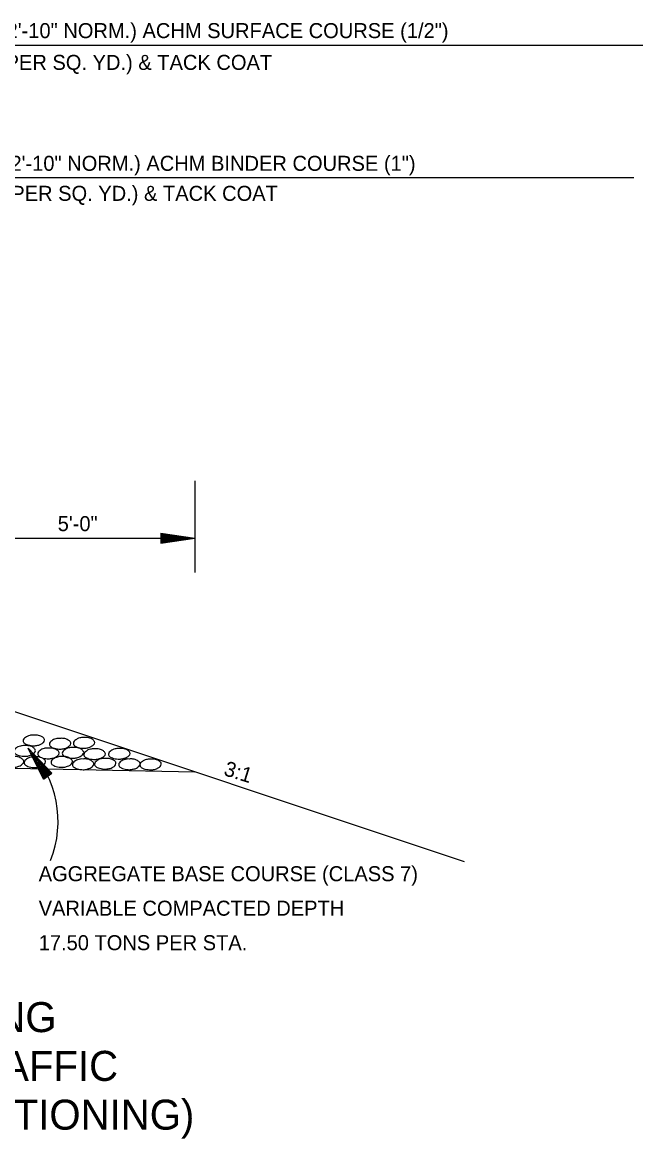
# Model space of a CAD drawing. Extents: x 635488 to 635865, y 290537 to 290973.
# Drawn here: x 635544.25 to 635569.05, y 290815.29 to 290859.93 of the extents above; entities that cross this region are included whole.
import ezdxf

# ---------------------------------------------------------------- set-up
doc = ezdxf.new("R2010")
doc.units = 0
doc.layers.add('Default', color=7, linetype='Continuous')

msp = doc.modelspace()

# ---------------------------------------------------------------- linework, layer by layer
at = {"layer": 'Default'}
for p, q in [((635569.047, 290859.005), (635537.821, 290859.005)), ((635568.697, 290853.718), (635538.128, 290853.718)), ((635551.153, 290841.602), (635551.153, 290837.937)), ((635549.785, 290839.511), (635551.153, 290839.307)), ((635549.785, 290839.511), (635549.785, 290839.101)), ((635549.785, 290839.478), (635550.924, 290839.307)), ((635542.16, 290839.307), (635551.153, 290839.307)), ((635549.785, 290839.442), (635550.687, 290839.307)), ((635549.785, 290839.409), (635550.458, 290839.307)), ((635549.785, 290839.372), (635550.227, 290839.307)), ((635549.785, 290839.339), (635549.998, 290839.307)), ((635549.785, 290839.101), (635551.153, 290839.307)), ((635549.785, 290839.238), (635550.227, 290839.307)), ((635549.785, 290839.169), (635550.687, 290839.307)), ((635549.785, 290839.135), (635550.924, 290839.307)), ((635549.785, 290839.205), (635550.458, 290839.307)), ((635549.785, 290839.274), (635549.998, 290839.307)), ((635542.16, 290832.959), (635561.914, 290826.375)), ((635512.523, 290830.734), (635551.153, 290829.962)), ((635545.095, 290829.669), (635544.483, 290830.911)), ((635545.433, 290829.906), (635544.483, 290830.911)), ((635545.123, 290829.687), (635544.615, 290830.724)), ((635545.405, 290829.882), (635544.615, 290830.724)), ((635545.376, 290829.865), (635544.749, 290830.529)), ((635545.153, 290829.708), (635544.749, 290830.529)), ((635545.182, 290829.728), (635544.878, 290830.342)), ((635545.347, 290829.843), (635544.878, 290830.342)), ((635545.319, 290829.825), (635545.012, 290830.152)), ((635545.21, 290829.75), (635545.012, 290830.152)), ((635545.095, 290829.669), (635545.433, 290829.906)), ((635545.29, 290829.804), (635545.142, 290829.966)), ((635545.238, 290829.767), (635545.142, 290829.966))]:
    msp.add_line(p, q, dxfattribs=at)
msp.add_arc((635541.498, 290827.979), 4.183, 337.9932, 44.4822, dxfattribs=at)
for points in [[(635544.705, 290831.429), (635544.858, 290831.428), (635545.04, 290831.364), (635545.129, 290831.281), (635545.141, 290831.227), (635545.095, 290831.135), (635545.043, 290831.096), (635544.943, 290831.044), (635544.797, 290831.01), (635544.721, 290831.002), (635544.61, 290831.013), (635544.484, 290831.034), (635544.389, 290831.071), (635544.301, 290831.144), (635544.286, 290831.202), (635544.312, 290831.284), (635544.382, 290831.337), (635544.446, 290831.379), (635544.548, 290831.414), (635544.611, 290831.428), (635544.705, 290831.429)], [(635544.342, 290831.008), (635544.49, 290831.007), (635544.674, 290830.944), (635544.761, 290830.857), (635544.777, 290830.807), (635544.73, 290830.714), (635544.676, 290830.673), (635544.577, 290830.625), (635544.431, 290830.587), (635544.353, 290830.583), (635544.244, 290830.589), (635544.119, 290830.609), (635544.024, 290830.65), (635543.935, 290830.72), (635543.921, 290830.779), (635543.949, 290830.862), (635544.018, 290830.918), (635544.079, 290830.961), (635544.182, 290830.991), (635544.246, 290831.007), (635544.342, 290831.008)], [(635545.753, 290831.298), (635545.904, 290831.297), (635546.086, 290831.233), (635546.178, 290831.147), (635546.192, 290831.097), (635546.142, 290831.004), (635546.09, 290830.962), (635545.993, 290830.913), (635545.842, 290830.876), (635545.768, 290830.871), (635545.655, 290830.879), (635545.533, 290830.901), (635545.438, 290830.94), (635545.349, 290831.01), (635545.335, 290831.072), (635545.362, 290831.15), (635545.43, 290831.206), (635545.496, 290831.25), (635545.594, 290831.283), (635545.656, 290831.297), (635545.753, 290831.298)], [(635546.71, 290831.33), (635546.861, 290831.328), (635547.045, 290831.266), (635547.132, 290831.18), (635547.146, 290831.13), (635547.098, 290831.035), (635547.047, 290830.995), (635546.947, 290830.946), (635546.8, 290830.909), (635546.724, 290830.904), (635546.613, 290830.912), (635546.489, 290830.934), (635546.392, 290830.973), (635546.303, 290831.043), (635546.291, 290831.101), (635546.319, 290831.183), (635546.388, 290831.238), (635546.45, 290831.281), (635546.551, 290831.316), (635546.615, 290831.328), (635546.71, 290831.33)], [(635543.875, 290830.569), (635544.026, 290830.568), (635544.208, 290830.504), (635544.3, 290830.418), (635544.314, 290830.368), (635544.264, 290830.275), (635544.211, 290830.233), (635544.115, 290830.184), (635543.964, 290830.147), (635543.89, 290830.142), (635543.777, 290830.15), (635543.655, 290830.172), (635543.56, 290830.211), (635543.471, 290830.281), (635543.457, 290830.343), (635543.484, 290830.421), (635543.552, 290830.477), (635543.618, 290830.521), (635543.716, 290830.554), (635543.778, 290830.568), (635543.875, 290830.569)], [(635544.746, 290830.56), (635544.897, 290830.558), (635545.079, 290830.494), (635545.171, 290830.408), (635545.185, 290830.358), (635545.135, 290830.265), (635545.082, 290830.223), (635544.986, 290830.175), (635544.834, 290830.137), (635544.761, 290830.133), (635544.647, 290830.14), (635544.526, 290830.162), (635544.431, 290830.201), (635544.342, 290830.271), (635544.328, 290830.334), (635544.355, 290830.411), (635544.423, 290830.468), (635544.489, 290830.511), (635544.587, 290830.544), (635544.649, 290830.558), (635544.746, 290830.56)], [(635545.286, 290830.91), (635545.437, 290830.909), (635545.619, 290830.845), (635545.711, 290830.759), (635545.725, 290830.709), (635545.675, 290830.616), (635545.623, 290830.574), (635545.526, 290830.526), (635545.375, 290830.488), (635545.302, 290830.483), (635545.188, 290830.491), (635545.066, 290830.513), (635544.971, 290830.552), (635544.882, 290830.622), (635544.868, 290830.684), (635544.895, 290830.762), (635544.963, 290830.818), (635545.029, 290830.862), (635545.127, 290830.895), (635545.189, 290830.909), (635545.286, 290830.91)], [(635545.821, 290830.569), (635545.972, 290830.568), (635546.155, 290830.504), (635546.247, 290830.418), (635546.261, 290830.368), (635546.211, 290830.275), (635546.158, 290830.233), (635546.061, 290830.184), (635545.91, 290830.147), (635545.837, 290830.142), (635545.723, 290830.15), (635545.601, 290830.172), (635545.506, 290830.211), (635545.418, 290830.281), (635545.404, 290830.343), (635545.43, 290830.421), (635545.499, 290830.477), (635545.564, 290830.521), (635545.662, 290830.554), (635545.725, 290830.568), (635545.821, 290830.569)], [(635546.269, 290830.932), (635546.42, 290830.93), (635546.604, 290830.868), (635546.692, 290830.78), (635546.704, 290830.731), (635546.659, 290830.639), (635546.606, 290830.595), (635546.506, 290830.548), (635546.358, 290830.512), (635546.285, 290830.505), (635546.171, 290830.514), (635546.046, 290830.534), (635545.954, 290830.573), (635545.863, 290830.643), (635545.85, 290830.703), (635545.878, 290830.785), (635545.945, 290830.84), (635546.009, 290830.885), (635546.11, 290830.916), (635546.174, 290830.93), (635546.269, 290830.932)], [(635547.135, 290830.881), (635547.284, 290830.88), (635547.465, 290830.817), (635547.556, 290830.73), (635547.571, 290830.682), (635547.523, 290830.588), (635547.468, 290830.545), (635547.37, 290830.5), (635547.222, 290830.464), (635547.147, 290830.456), (635547.038, 290830.465), (635546.912, 290830.486), (635546.818, 290830.523), (635546.727, 290830.593), (635546.714, 290830.654), (635546.742, 290830.736), (635546.811, 290830.791), (635546.873, 290830.835), (635546.974, 290830.864), (635547.04, 290830.88), (635547.135, 290830.881)], [(635548.119, 290830.893), (635548.27, 290830.892), (635548.454, 290830.831), (635548.543, 290830.744), (635548.557, 290830.695), (635548.508, 290830.599), (635548.455, 290830.558), (635548.356, 290830.513), (635548.208, 290830.476), (635548.134, 290830.469), (635548.021, 290830.477), (635547.897, 290830.498), (635547.804, 290830.536), (635547.712, 290830.608), (635547.701, 290830.666), (635547.728, 290830.747), (635547.795, 290830.803), (635547.86, 290830.847), (635547.96, 290830.879), (635548.024, 290830.892), (635548.119, 290830.893)], [(635546.673, 290830.473), (635546.824, 290830.472), (635547.007, 290830.408), (635547.098, 290830.322), (635547.112, 290830.272), (635547.063, 290830.179), (635547.01, 290830.137), (635546.913, 290830.088), (635546.762, 290830.051), (635546.689, 290830.046), (635546.575, 290830.054), (635546.453, 290830.076), (635546.358, 290830.115), (635546.269, 290830.185), (635546.255, 290830.247), (635546.282, 290830.325), (635546.35, 290830.381), (635546.416, 290830.425), (635546.514, 290830.458), (635546.576, 290830.472), (635546.673, 290830.473)], [(635547.559, 290830.497), (635547.71, 290830.495), (635547.891, 290830.433), (635547.983, 290830.345), (635547.994, 290830.297), (635547.948, 290830.202), (635547.895, 290830.162), (635547.797, 290830.113), (635547.648, 290830.076), (635547.573, 290830.07), (635547.461, 290830.081), (635547.338, 290830.101), (635547.241, 290830.138), (635547.154, 290830.211), (635547.138, 290830.269), (635547.165, 290830.35), (635547.235, 290830.406), (635547.299, 290830.448), (635547.401, 290830.481), (635547.462, 290830.495), (635547.559, 290830.497)], [(635548.524, 290830.473), (635548.674, 290830.472), (635548.856, 290830.408), (635548.948, 290830.324), (635548.961, 290830.271), (635548.912, 290830.179), (635548.858, 290830.137), (635548.763, 290830.087), (635548.611, 290830.056), (635548.538, 290830.045), (635548.424, 290830.057), (635548.303, 290830.077), (635548.209, 290830.116), (635548.119, 290830.185), (635548.103, 290830.246), (635548.132, 290830.327), (635548.2, 290830.383), (635548.266, 290830.425), (635548.364, 290830.456), (635548.426, 290830.472), (635548.524, 290830.473)], [(635549.372, 290830.466), (635549.525, 290830.465), (635549.707, 290830.401), (635549.796, 290830.318), (635549.808, 290830.264), (635549.762, 290830.172), (635549.71, 290830.133), (635549.61, 290830.081), (635549.464, 290830.047), (635549.388, 290830.039), (635549.277, 290830.05), (635549.151, 290830.071), (635549.056, 290830.108), (635548.968, 290830.181), (635548.953, 290830.239), (635548.979, 290830.321), (635549.049, 290830.374), (635549.113, 290830.416), (635549.215, 290830.451), (635549.278, 290830.465), (635549.372, 290830.466)]]:
    msp.add_spline(points, degree=3, dxfattribs=at)

# ---------------------------------------------------------------- texts
for s, height, p in [('VAR. (12\'-10" NORM.) ACHM SURFACE COURSE (1/2")', 0.6, (635540.815, 290859.302)), ('(XXX LBS. PER SQ. YD.) & TACK COAT', 0.6, (635539.525, 290858.032)), ('VAR. (12\'-10" NORM.) ACHM BINDER COURSE (1")', 0.6, (635540.97, 290853.995)), ('(XXX LBS. PER SQ. YD.) & TACK COAT', 0.6, (635539.753, 290852.795)), ('5\'-0"', 0.6, (635545.666, 290839.587)), ('AGGREGATE BASE COURSE (CLASS 7)', 0.6, (635544.906, 290825.587)), ('VARIABLE COMPACTED DEPTH', 0.6, (635544.906, 290824.208)), ('17.50 TONS PER STA.', 0.6, (635544.906, 290822.829)), ('ADDITIONAL WIDENING ', 1.2, (635527.344, 290819.552)), ('FOR MAINTENANCE OF TRAFFIC', 1.2, (635522.673, 290817.602)), ('(SHOWN IN DIRECTION OF STATIONING)', 1.2, (635519.659, 290815.652))]:
    msp.add_text(s, height=height, dxfattribs=at).set_placement(p)
msp.add_text('3:1', height=0.6, rotation=342.7185, dxfattribs=at).set_placement((635552.266, 290829.836))

doc.saveas('drawing.dxf')
